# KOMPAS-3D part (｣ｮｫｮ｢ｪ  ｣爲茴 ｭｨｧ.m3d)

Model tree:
1. Эскиз:1
2. Операция выдавливания:1
     Расстояние 1 = 2
3. Эскиз:2
4. Операция выдавливания:2
     Расстояние 1 = 12.6
5. Эскиз:3
6. Вырезать элемент выдавливания:1
     Расстояние 1 = 12.6
7. Эскиз:4
8. Вырезать элемент выдавливания:2
     Расстояние 1 = 12.6
9. Эскиз:5
10. Операция выдавливания:3
     Расстояние 1 = 3
11. Эскиз:6
12. Операция выдавливания:4
     Расстояние 1 = 3
13. Эскиз:7
14. Операция выдавливания:5
     Расстояние 1 = 2; Расстояние 2 = 14.6
15. Эскиз:8
16. Вырезать элемент выдавливания:3
     Расстояние 1 = 92.6
17. Эскиз:9
18. Вырезать элемент выдавливания:4
     Расстояние 1 = 2
